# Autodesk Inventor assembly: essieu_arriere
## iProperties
Created: 2011-01
Part Number: essieu_arriere
Document SubType Name: Assembly
Designer: eric
Mass: 6204.37 g
Surface Area: 10780.2 cm^2
Volume: 6204.37 cm^3
Density: 1 g/cm^3
Author: eric
